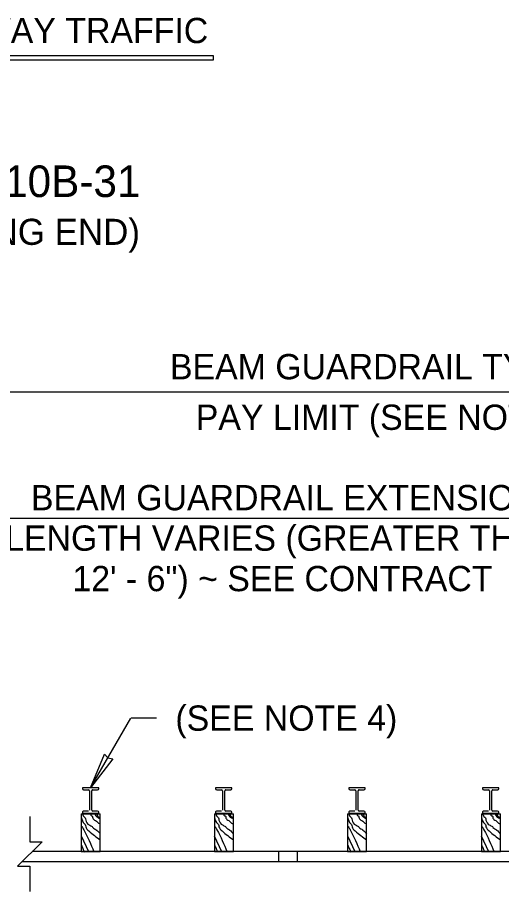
# Model space of a CAD drawing. Extents: x 99862 to 103680, y 99470 to 102076.
# Drawn here: x 100972 to 101278, y 100317 to 100870 of the extents above; entities that cross this region are included whole.
import ezdxf

# ---------------------------------------------------------------- set-up
doc = ezdxf.new("R2010")
doc.units = 0
for name, color, linetype in [('Level 1', 7, 'Continuous'), ('Level 10', 7, 'Continuous'), ('Level 11', 7, 'Continuous'), ('Level 13', 7, 'Continuous'), ('Level 15', 7, 'Continuous'), ('Level 20', 7, 'Continuous'), ('Level 3', 7, 'Continuous'), ('Level 4', 7, 'Continuous'), ('Level 9', 7, 'Continuous')]:
    doc.layers.add(name, color=color, linetype=linetype)

msp = doc.modelspace()

# ---------------------------------------------------------------- linework, layer by layer
at = {"layer": 'Level 1'}
for p, q in [((101492.93, 100342.5), (100981.02, 100342.5)), ((101486.32, 100335.89), (100974.41, 100335.89))]:
    msp.add_line(p, q, dxfattribs=at)
at = {"layer": 'Level 10'}
for p, q in [((101011.98, 100366.37), (101023.98, 100366.37)), ((101011.98, 100366.37), (101011.98, 100342.37)), ((101023.98, 100342.37), (101023.98, 100366.37)), ((101096.16, 100366.37), (101108.16, 100366.37)), ((101096.16, 100366.37), (101096.16, 100342.37)), ((101108.16, 100342.37), (101108.16, 100366.37)), ((101180.33, 100366.37), (101192.33, 100366.37)), ((101180.33, 100366.37), (101180.33, 100342.37)), ((101192.33, 100342.37), (101192.33, 100366.37)), ((101264.91, 100366.37), (101276.91, 100366.37)), ((101264.91, 100366.37), (101264.91, 100342.37)), ((101276.91, 100342.37), (101276.91, 100366.37)), ((101011.98, 100342.37), (101023.98, 100342.37)), ((101017.04, 100342.29), (101017.04, 100342.37)), ((101017.04, 100342.29), (101017.04, 100342.37)), ((101018.92, 100342.37), (101018.92, 100342.29)), ((101018.92, 100342.37), (101018.92, 100342.29)), ((101096.16, 100342.37), (101108.16, 100342.37)), ((101101.22, 100342.29), (101101.22, 100342.37)), ((101101.22, 100342.29), (101101.22, 100342.37)), ((101103.09, 100342.37), (101103.09, 100342.29)), ((101103.09, 100342.37), (101103.09, 100342.29)), ((101180.33, 100342.37), (101192.33, 100342.37)), ((101185.4, 100342.29), (101185.4, 100342.37)), ((101185.4, 100342.29), (101185.4, 100342.37)), ((101187.27, 100342.37), (101187.27, 100342.29)), ((101187.27, 100342.37), (101187.27, 100342.29)), ((101264.91, 100342.37), (101276.91, 100342.37)), ((101269.97, 100342.29), (101269.97, 100342.37)), ((101269.97, 100342.29), (101269.97, 100342.37)), ((101271.84, 100342.37), (101271.84, 100342.29)), ((101271.84, 100342.37), (101271.84, 100342.29))]:
    msp.add_line(p, q, dxfattribs=at)
at = {"layer": 'Level 11'}
for p, q in [((101136.68, 100342.5), (101136.68, 100335.89)), ((101148.45, 100342.5), (101148.45, 100335.89))]:
    msp.add_line(p, q, dxfattribs=at)
at = {"layer": 'Level 13'}
for p, q in [((101011.85, 100352.46), (101016.45, 100342.45)), ((101096.03, 100352.46), (101100.63, 100342.45)), ((101180.21, 100352.46), (101184.8, 100342.45)), ((101264.78, 100352.46), (101269.38, 100342.45))]:
    msp.add_line(p, q, dxfattribs=at)
for points in [[(101012.74, 100366.36), (101014.01, 100364.09), (101014.46, 100363.68), (101014.82, 100362.29), (101016.94, 100359.27), (101018.85, 100358.18), (101019.26, 100357.64), (101021.39, 100356.18), (101021.57, 100356.05), (101023.99, 100353.76)], [(101017.71, 100366.36), (101018.52, 100365.01), (101018.92, 100364.84), (101019.09, 100364.13), (101020.33, 100362.36), (101021.57, 100361.7), (101021.9, 100361.27), (101023.96, 100359.86)], [(101020.4, 100366.38), (101020.82, 100365.69), (101021.72, 100364.4), (101022.71, 100363.81), (101023.88, 100363.07)], [(101021.81, 100366.35), (101022.17, 100365.03), (101023.88, 100363.9)], [(101096.91, 100366.36), (101098.19, 100364.09), (101098.64, 100363.68), (101098.99, 100362.29), (101101.12, 100359.27), (101103.03, 100358.18), (101103.44, 100357.64), (101105.57, 100356.18), (101105.75, 100356.05), (101108.17, 100353.76)], [(101101.88, 100366.36), (101102.7, 100365.01), (101103.1, 100364.84), (101103.27, 100364.13), (101104.51, 100362.36), (101105.75, 100361.7), (101106.07, 100361.27), (101108.13, 100359.86)], [(101104.58, 100366.38), (101104.99, 100365.69), (101105.9, 100364.4), (101106.89, 100363.81), (101108.06, 100363.07)], [(101105.99, 100366.35), (101106.35, 100365.03), (101108.06, 100363.9)], [(101181.09, 100366.36), (101182.37, 100364.09), (101182.82, 100363.68), (101183.17, 100362.29), (101185.3, 100359.27), (101187.21, 100358.18), (101187.62, 100357.64), (101189.75, 100356.18), (101189.93, 100356.05), (101192.35, 100353.76)], [(101186.06, 100366.36), (101186.88, 100365.01), (101187.28, 100364.84), (101187.44, 100364.13), (101188.69, 100362.36), (101189.92, 100361.7), (101190.25, 100361.27), (101192.31, 100359.86)], [(101188.76, 100366.38), (101189.17, 100365.69), (101190.08, 100364.4), (101191.06, 100363.81), (101192.24, 100363.07)], [(101190.17, 100366.35), (101190.53, 100365.03), (101192.23, 100363.9)], [(101265.66, 100366.36), (101266.94, 100364.09), (101267.39, 100363.68), (101267.74, 100362.29), (101269.87, 100359.27), (101271.78, 100358.18), (101272.19, 100357.64), (101274.32, 100356.18), (101274.5, 100356.05), (101276.92, 100353.76)], [(101270.63, 100366.36), (101271.45, 100365.01), (101271.85, 100364.84), (101272.02, 100364.13), (101273.26, 100362.36), (101274.5, 100361.7), (101274.82, 100361.27), (101276.88, 100359.86)], [(101273.33, 100366.38), (101273.74, 100365.69), (101274.65, 100364.4), (101275.64, 100363.81), (101276.81, 100363.07)], [(101274.74, 100366.35), (101275.1, 100365.03), (101276.81, 100363.9)], [(101011.92, 100364.11), (101014.02, 100359.96), (101014.47, 100359.56), (101014.82, 100358.17), (101016.77, 100355.45), (101023.98, 100349.86)], [(101096.1, 100364.11), (101098.2, 100359.96), (101098.65, 100359.56), (101099, 100358.17), (101100.95, 100355.45), (101108.16, 100349.86)], [(101180.28, 100364.11), (101182.37, 100359.96), (101182.82, 100359.56), (101183.18, 100358.17), (101185.13, 100355.45), (101192.33, 100349.86)], [(101264.85, 100364.11), (101266.95, 100359.96), (101267.4, 100359.56), (101267.75, 100358.17), (101269.7, 100355.45), (101276.91, 100349.86)], [(101012.38, 100358.25), (101013.53, 100356.24), (101019.94, 100342.31)], [(101096.56, 100358.25), (101097.71, 100356.24), (101104.12, 100342.31)], [(101180.74, 100358.25), (101181.88, 100356.24), (101188.3, 100342.31)], [(101265.31, 100358.25), (101266.46, 100356.24), (101272.87, 100342.31)], [(101011.96, 100346.54), (101012.11, 100346.28), (101012.26, 100346.01), (101012.53, 100345.47), (101013.02, 100344.36), (101013.47, 100343.23), (101013.7, 100342.67), (101013.95, 100342.11)], [(101096.14, 100346.54), (101096.29, 100346.28), (101096.43, 100346.01), (101096.71, 100345.47), (101097.19, 100344.36), (101097.65, 100343.23), (101097.88, 100342.67), (101098.12, 100342.11)], [(101180.31, 100346.54), (101180.47, 100346.28), (101180.61, 100346.01), (101180.88, 100345.47), (101181.37, 100344.36), (101181.83, 100343.23), (101182.06, 100342.67), (101182.3, 100342.11)], [(101264.89, 100346.54), (101265.04, 100346.28), (101265.18, 100346.01), (101265.46, 100345.47), (101265.94, 100344.36), (101266.4, 100343.23), (101266.63, 100342.67), (101266.87, 100342.11)]]:
    msp.add_spline(points, degree=3, dxfattribs=at)
at = {"layer": 'Level 15'}
for p, q in [((101017.85, 100382.8), (101043.3, 100426.87)), ((101059.44, 100426.87), (101043.44, 100426.87))]:
    msp.add_line(p, q, dxfattribs=at)
msp.add_lwpolyline([(101017.85, 100382.8), (101026.68, 100404.07), (101028.74, 100401.66), (101031.85, 100401.08)], close=True, dxfattribs=at)
msp.add_lwpolyline([(100979.39, 100364.62), (100979.39, 100348.62), (100987.14, 100348.62), (100971.65, 100333.13), (100979.39, 100333.13), (100979.39, 100317.13)], dxfattribs=at)
at = {"layer": 'Level 20'}
for p, q in [((100933.41, 100633.28), (101491.3, 100633.28)), ((100933.41, 100553.33), (101355.28, 100553.33))]:
    msp.add_line(p, q, dxfattribs=at)
at = {"layer": 'Level 3'}
msp.add_lwpolyline([(101095.52, 100846.02), (100874.78, 100846.02), (100880.48, 100855.87), (100810.51, 100843.54), (101095.52, 100843.54)], close=True, dxfattribs=at)
at = {"layer": 'Level 4'}
msp.add_line((101182.03, 100342.37), (101191.03, 100342.37), dxfattribs=at)
at = {"layer": 'Level 9'}
for p, q in [((101017.08, 100380.94), (101017.07, 100374.81)), ((101018.62, 100374.8), (101018.62, 100380.94)), ((101101.26, 100380.94), (101101.25, 100374.81)), ((101102.79, 100374.8), (101102.8, 100380.94)), ((101185.44, 100380.94), (101185.43, 100374.81)), ((101186.97, 100374.8), (101186.98, 100380.94)), ((101270.01, 100380.94), (101270, 100374.81)), ((101271.54, 100374.8), (101271.55, 100380.94)), ((101017.07, 100374.81), (101017.06, 100368.67)), ((101018.61, 100368.67), (101018.62, 100374.8)), ((101101.25, 100374.81), (101101.24, 100368.67)), ((101102.79, 100368.67), (101102.79, 100374.8)), ((101185.43, 100374.81), (101185.42, 100368.67)), ((101186.96, 100368.67), (101186.97, 100374.8)), ((101270, 100374.81), (101269.99, 100368.67)), ((101271.54, 100368.67), (101271.54, 100374.8))]:
    msp.add_line(p, q, dxfattribs=at)
for points in [[(101017.85, 100382.8), (101012.68, 100382.81), (101012.68, 100382.33)], [(101013.47, 100381.54), (101016.49, 100381.53)], [(101023.02, 100382.31), (101023.02, 100382.8), (101017.85, 100382.8)], [(101019.21, 100381.53), (101022.23, 100381.53)], [(101102.03, 100382.8), (101096.86, 100382.81), (101096.86, 100382.33)], [(101097.65, 100381.54), (101100.67, 100381.53)], [(101107.2, 100382.31), (101107.2, 100382.8), (101102.03, 100382.8)], [(101103.39, 100381.53), (101106.41, 100381.53)], [(101186.21, 100382.8), (101181.04, 100382.81), (101181.04, 100382.33)], [(101181.83, 100381.54), (101184.85, 100381.53)], [(101191.38, 100382.31), (101191.38, 100382.8), (101186.21, 100382.8)], [(101187.57, 100381.53), (101190.59, 100381.53)], [(101270.78, 100382.8), (101265.61, 100382.81), (101265.61, 100382.33)], [(101266.4, 100381.54), (101269.42, 100381.53)], [(101275.95, 100382.31), (101275.95, 100382.8), (101270.78, 100382.8)], [(101272.14, 100381.53), (101275.16, 100381.53)], [(101012.67, 100367.29), (101012.66, 100366.81), (101017.83, 100366.8)], [(101016.47, 100368.08), (101013.45, 100368.08)], [(101017.83, 100366.8), (101023, 100366.8), (101023, 100367.28)], [(101022.22, 100368.07), (101019.2, 100368.07)], [(101096.84, 100367.29), (101096.84, 100366.81), (101102.01, 100366.8)], [(101100.65, 100368.08), (101097.63, 100368.08)], [(101102.01, 100366.8), (101107.18, 100366.8), (101107.18, 100367.28)], [(101106.39, 100368.07), (101103.38, 100368.07)], [(101181.02, 100367.29), (101181.02, 100366.81), (101186.19, 100366.8)], [(101184.83, 100368.08), (101181.81, 100368.08)], [(101186.19, 100366.8), (101191.36, 100366.8), (101191.36, 100367.28)], [(101190.57, 100368.07), (101187.55, 100368.07)], [(101265.59, 100367.29), (101265.59, 100366.81), (101270.76, 100366.8)], [(101269.4, 100368.08), (101266.38, 100368.08)], [(101270.76, 100366.8), (101275.93, 100366.8), (101275.93, 100367.28)], [(101275.14, 100368.07), (101272.13, 100368.07)]]:
    msp.add_lwpolyline(points, dxfattribs=at)
for centre, radius, start, end in [((101013.47, 100382.33), 0.788, 179.9273, 269.9273), ((101016.49, 100380.94), 0.591, 359.9273, 89.9273), ((101019.21, 100380.94), 0.591, 89.9273, 179.9273), ((101022.24, 100382.31), 0.788, 269.9273, 359.9273), ((101097.65, 100382.33), 0.788, 179.9273, 269.9273), ((101100.67, 100380.94), 0.591, 359.9273, 89.9273), ((101103.39, 100380.94), 0.591, 89.9273, 179.9273), ((101106.41, 100382.31), 0.788, 269.9273, 359.9273), ((101181.83, 100382.33), 0.788, 179.9273, 269.9273), ((101184.85, 100380.94), 0.591, 359.9273, 89.9273), ((101187.57, 100380.94), 0.591, 89.9273, 179.9273), ((101190.59, 100382.31), 0.788, 269.9273, 359.9273), ((101266.4, 100382.33), 0.788, 179.9273, 269.9273), ((101269.42, 100380.94), 0.591, 359.9273, 89.9273), ((101272.14, 100380.94), 0.591, 89.9273, 179.9273), ((101275.16, 100382.31), 0.788, 269.9273, 359.9273), ((101013.45, 100367.29), 0.788, 89.9273, 179.9478), ((101019.2, 100368.66), 0.591, 179.9273, 269.9273), ((101022.22, 100367.28), 0.788, 359.9478, 89.9273), ((101097.63, 100367.29), 0.788, 89.9273, 179.9478), ((101103.38, 100368.66), 0.591, 179.9273, 269.9273), ((101106.39, 100367.28), 0.788, 359.9478, 89.9273), ((101181.81, 100367.29), 0.788, 89.9273, 179.9478), ((101187.55, 100368.66), 0.591, 179.9273, 269.9273), ((101190.57, 100367.28), 0.788, 359.9478, 89.9273), ((101266.38, 100367.29), 0.788, 89.9273, 179.9478), ((101272.13, 100368.66), 0.591, 179.9273, 269.9273), ((101275.14, 100367.28), 0.788, 359.9478, 89.9273)]:
    msp.add_arc(centre, radius, start, end, dxfattribs=at)

# ---------------------------------------------------------------- texts
at = {"layer": 'Level 20'}
for s, height, p in [('ONE-WAY TRAFFIC', 16, (100893.71, 100854.02)), ('CASE 10B-31', 20, (100882.89, 100756.62)), ('BEAM GUARDRAIL TYPE 31 ', 16, (101068.02, 100641.28)), ('PAY LIMIT (SEE NOTE 1)', 16, (101084.33, 100609.28)), ('BEAM GUARDRAIL EXTENSION', 16, (100980.13, 100558.39)), ('LENGTH VARIES (GREATER THAN ', 16, (100963.84, 100532.79)), ('12\' - 6") ~ SEE CONTRACT', 16, (101006.35, 100507.19))]:
    msp.add_text(s, height=height, dxfattribs=at).set_placement(p)
for s, height, rotation, p in [('(TRAILING END)', 16.5, 0, (100879.9, 100726.37)), ('(SEE NOTE 4)', 16, 360, (101071.44, 100418.87))]:
    msp.add_text(s, height=height, rotation=rotation, dxfattribs=at).set_placement(p)

doc.saveas('drawing.dxf')
